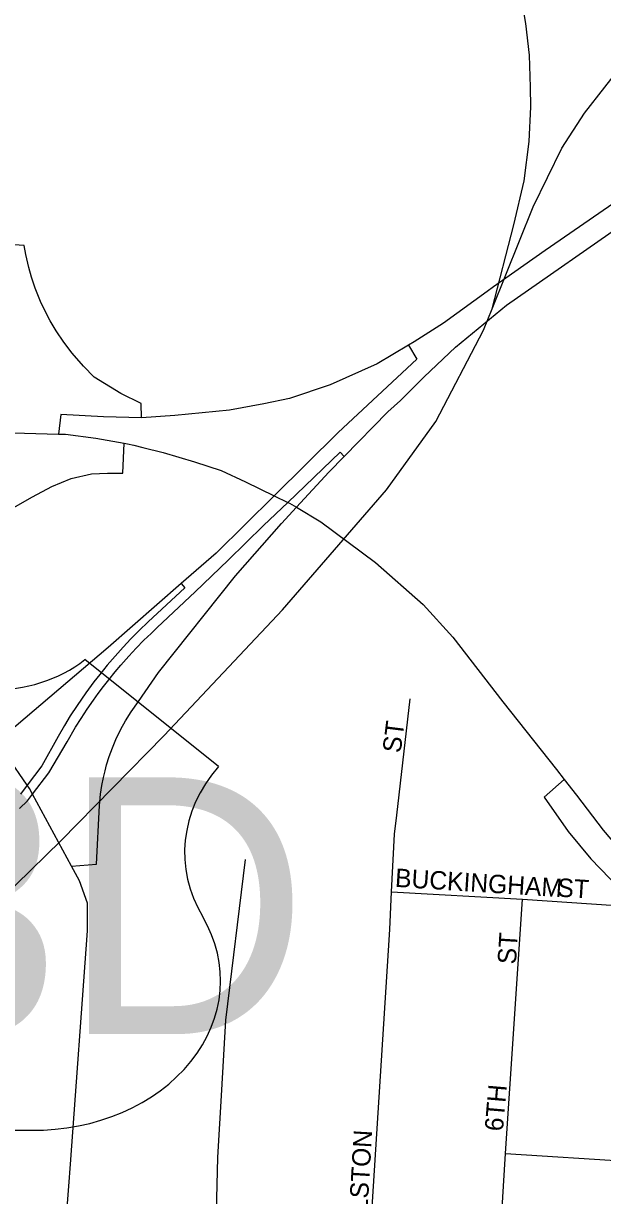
# Model space of a CAD drawing. Extents: x 0 to 34, y -6.2 to 22.
# Drawn here: x 6.817 to 7.114, y 18.6 to 19.202 of the extents above; entities that cross this region are included whole.
import ezdxf

# ---------------------------------------------------------------- set-up
doc = ezdxf.new("R2010")
doc.units = 0
for name, color, linetype in [('GM_X_City_Street', 7, 'Continuous'), ('GM_X_City_Street_Text', 7, 'Continuous'), ('GM_X_Interchange_Ramps', 7, 'Continuous'), ('GM_X_Interstate_Route', 7, 'Continuous'), ('GM_X_Rail_Line', 7, 'Continuous'), ('GM_X_US_Route', 7, 'Continuous'), ('GM_X_US_Shield', 7, 'Continuous')]:
    doc.layers.add(name, color=color, linetype=linetype)

msp = doc.modelspace()

# ---------------------------------------------------------------- linework, layer by layer
at = {"layer": 'GM_X_City_Street'}
for points in [[(7.00828, 18.79563), (7.0151, 18.85549)], [(6.98852, 18.50512), (6.99217, 18.55056), (6.99568, 18.59432), (7.00463, 18.73692), (7.00564, 18.75627), (7.00717, 18.78589), (7.00828, 18.79563)], [(6.9184, 18.65465), (6.92051, 18.69039), (6.93063, 18.77297)], [(7.00564, 18.75627), (7.07288, 18.75262), (7.12097, 18.74924)], [(7.0591, 18.54649), (7.06178, 18.5827), (7.06414, 18.62187), (7.07288, 18.75262)], [(6.91261, 18.50619), (6.9125, 18.50861), (6.9148, 18.55673), (6.91634, 18.61984), (6.9184, 18.65465)], [(7.06414, 18.62187), (7.12864, 18.61789), (7.21273, 18.61353)]]:
    msp.add_lwpolyline(points, dxfattribs=at)
at = {"layer": 'GM_X_Interchange_Ramps'}
for points in [[(7.12196, 19.11144), (7.08457, 19.08567), (7.05797, 19.06696), (7.05463, 19.06454), (7.0322, 19.04826), (7.01725, 19.0387), (7.01434, 19.03699), (6.99813, 19.02748), (6.97402, 19.01666), (6.95324, 19.0096), (6.94005, 19.00696), (6.92231, 19.00369), (6.89424, 19.00087), (6.8771, 18.99963), (6.85772, 19.00022), (6.83566, 19.00143), (6.83458, 18.9914)], [(6.84122, 18.7695), (6.85396, 18.77052), (6.85555, 18.8006), (6.85612, 18.8064), (6.8568, 18.8109), (6.85762, 18.81502), (6.85844, 18.8185), (6.85925, 18.82148), (6.8606, 18.82579), (6.8622, 18.83017), (6.864, 18.83447), (6.86659, 18.83984), (6.86891, 18.84404), (6.87187, 18.84881), (6.8756, 18.85409), (6.88596, 18.86897), (6.92536, 18.91862), (6.94899, 18.94542), (6.95672, 18.95377), (6.97342, 18.97183), (6.98132, 18.97993), (7.00372, 19.00288), (7.01024, 19.00866), (7.0224, 19.02084), (7.03841, 19.03606), (7.06463, 19.05765), (7.12844, 19.102)], [(6.8771, 18.99963), (6.87695, 19.00714), (6.86656, 19.01226), (6.85277, 19.02055), (6.84735, 19.02633), (6.8415, 19.03297), (6.8372, 19.03859), (6.83326, 19.04445), (6.83027, 19.04948), (6.82765, 19.05446), (6.82533, 19.05941), (6.82256, 19.06631), (6.82068, 19.07192), (6.81926, 19.07698), (6.81776, 19.08363), (6.81692, 19.08821), (6.81172, 19.08851)], [(7.01434, 19.03699), (7.0185, 19.0299), (6.97819, 18.99215), (6.94534, 18.9597), (6.91555, 18.93028), (6.89756, 18.91457), (6.86001, 18.88181), (6.80478, 18.83478)], [(6.71787, 18.98609), (6.72073, 18.98655), (6.72404, 18.97839), (6.7294, 18.96517), (6.73165, 18.96114), (6.73869, 18.95372), (6.74784, 18.94705), (6.75971, 18.94231), (6.76655, 18.94109), (6.77276, 18.94074), (6.78077, 18.94138), (6.78833, 18.94329), (6.80077, 18.94752), (6.80272, 18.94862), (6.82125, 18.95911), (6.83105, 18.96437), (6.84108, 18.96853), (6.85151, 18.97094), (6.85973, 18.97133), (6.86755, 18.97133), (6.86827, 18.98674)], [(6.81444, 18.79903), (6.81858, 18.80309), (6.82117, 18.80646), (6.82954, 18.81734), (6.83892, 18.8334), (6.84327, 18.84083), (6.84612, 18.84538), (6.84927, 18.85017), (6.85245, 18.85476), (6.85498, 18.85824), (6.85763, 18.86177), (6.86033, 18.86522), (6.86361, 18.86925), (6.86653, 18.87269), (6.87068, 18.87737), (6.87446, 18.88142), (6.87844, 18.88548), (6.88209, 18.88905), (6.88525, 18.89202), (6.90476, 18.91043), (6.92175, 18.9266), (6.93987, 18.94444), (6.95228, 18.95632), (6.97915, 18.98206), (6.98132, 18.97993)], [(6.89756, 18.91457), (6.89947, 18.91238), (6.88062, 18.89499), (6.87592, 18.89049), (6.87163, 18.88616), (6.8677, 18.88201), (6.86357, 18.8774), (6.85949, 18.87264), (6.8557, 18.86797), (6.85272, 18.86412), (6.84853, 18.85844), (6.84406, 18.85197), (6.84059, 18.84662), (6.83763, 18.8418), (6.83427, 18.83602), (6.82591, 18.82096), (6.81846, 18.81102), (6.81505, 18.80647)], [(7.09428, 18.814), (7.08391, 18.80494), (7.09639, 18.78733), (7.10791, 18.77326), (7.12743, 18.7531), (7.14566, 18.73806), (7.16327, 18.72622), (7.18823, 18.71246), (7.21159, 18.70158), (7.21818, 18.70031)]]:
    msp.add_lwpolyline(points, dxfattribs=at)
at = {"layer": 'GM_X_Interstate_Route'}
for points in [[(6.80545, 18.99217), (6.83458, 18.9914), (6.83806, 18.99131), (6.85371, 18.98932), (6.86827, 18.98674), (6.86995, 18.98639), (6.87322, 18.9857), (6.87776, 18.98454)], [(6.87776, 18.98454), (6.8883, 18.98184), (6.90431, 18.97717), (6.91809, 18.97273), (6.93063, 18.96687), (6.94534, 18.9597), (6.95228, 18.95632), (6.95326, 18.95584), (6.95672, 18.95377), (6.96924, 18.94632), (6.99734, 18.92542), (7.0218, 18.90391), (7.037, 18.88702), (7.06279, 18.85383), (7.09032, 18.81914), (7.09428, 18.814), (7.10052, 18.80588)], [(7.10052, 18.80588), (7.11435, 18.78791), (7.12902, 18.77063), (7.15269, 18.74908), (7.17518, 18.73464), (7.19169, 18.72517), (7.21899, 18.71164)]]:
    msp.add_lwpolyline(points, dxfattribs=at)
at = {"layer": 'GM_X_Rail_Line'}
for points in [[(7.05723, 19.05565), (7.06847, 19.0988), (7.07365, 19.12137), (7.07624, 19.1416), (7.0771, 19.15937), (7.07698, 19.1696), (7.07648, 19.18601), (7.07463, 19.20217), (7.07143, 19.22055), (7.0676, 19.23498), (7.06255, 19.25299), (7.05663, 19.26804), (7.03751, 19.31331), (7.02443, 19.35006), (7.02011, 19.36844), (7.01715, 19.38411), (7.01481, 19.40459), (7.01395, 19.43481), (7.01469, 19.48106), (7.0153, 19.51634), (7.0153, 19.52707)], [(7.05723, 19.05565), (7.07835, 19.10807), (7.09312, 19.13827), (7.10465, 19.15613), (7.12552, 19.18291), (7.14134, 19.19958), (7.1585, 19.21434), (7.172, 19.22474), (7.18676, 19.2343), (7.20138, 19.24274), (7.2191, 19.25132), (7.23864, 19.25933), (7.2557, 19.26448)], [(6.83574, 18.78249), (6.88885, 18.83651), (6.94956, 18.90105), (7.00292, 18.96272), (7.02833, 18.99775), (7.05283, 19.04474), (7.05723, 19.05565)], [(6.65213, 18.63903), (6.69073, 18.66651), (6.79043, 18.74001), (6.80513, 18.75247), (6.83574, 18.78249)]]:
    msp.add_lwpolyline(points, dxfattribs=at)
at = {"layer": 'GM_X_US_Route'}
for points in [[(6.84935, 18.75055), (6.84535, 18.76188), (6.84122, 18.7695), (6.82117, 18.80646), (6.81961, 18.80932), (6.81846, 18.81102), (6.80837, 18.82578), (6.80478, 18.83478), (6.80428, 18.83603), (6.79864, 18.8558), (6.79864, 18.88273)], [(6.84067, 18.61639), (6.84939, 18.73633), (6.84939, 18.75045), (6.84935, 18.75055)], [(6.85988, 18.36813), (6.85988, 18.36813), (6.85609, 18.3923), (6.85217, 18.41434), (6.84368, 18.46204), (6.8361, 18.5132), (6.83481, 18.54114), (6.83986, 18.60517), (6.84067, 18.61639)]]:
    msp.add_lwpolyline(points, dxfattribs=at)
at = {"layer": 'GM_X_US_Shield'}
for p, q in [((6.9167, 18.82061), (6.84803, 18.87554)), ((6.80683, 18.63384), (6.82057, 18.63384))]:
    msp.add_line(p, q, dxfattribs=at)
for centre, major_axis, start_param, end_param in [((6.79997, 18.91477), (-0.06866, 0), 0.795399, 2.346194), ((6.99544, 18.7765), (-0.09613, 0), 5.672304, 6.727422), ((6.82164, 18.71074), (-0.09613, 0), 1.559657, 3.580859)]:
    msp.add_ellipse(centre, major_axis=major_axis, ratio=0.8, start_param=start_param, end_param=end_param, dxfattribs=at)

# ---------------------------------------------------------------- texts
at = {"layer": 'GM_X_City_Street_Text'}
for s, rotation, p in [('ST', 82.88002, (7.0103, 18.82733)), ('BUCKINGHAM', 356.4248, (7.00718, 18.7589)), ('ST', 356.41176, (7.09052, 18.7539)), ('ST', 86.41175, (7.06946, 18.71889)), ('6TH', 85.09736, (7.0628, 18.6331)), ('NEILSTON', 86.63221, (6.99196, 18.57055))]:
    msp.add_text(s, height=0.00947, rotation=rotation, dxfattribs=at).set_placement(p)
at = {"layer": 'GM_X_US_Shield'}
msp.add_text('23D', height=0.131836, dxfattribs=at).set_placement((6.63971, 18.68328))

doc.saveas('drawing.dxf')
